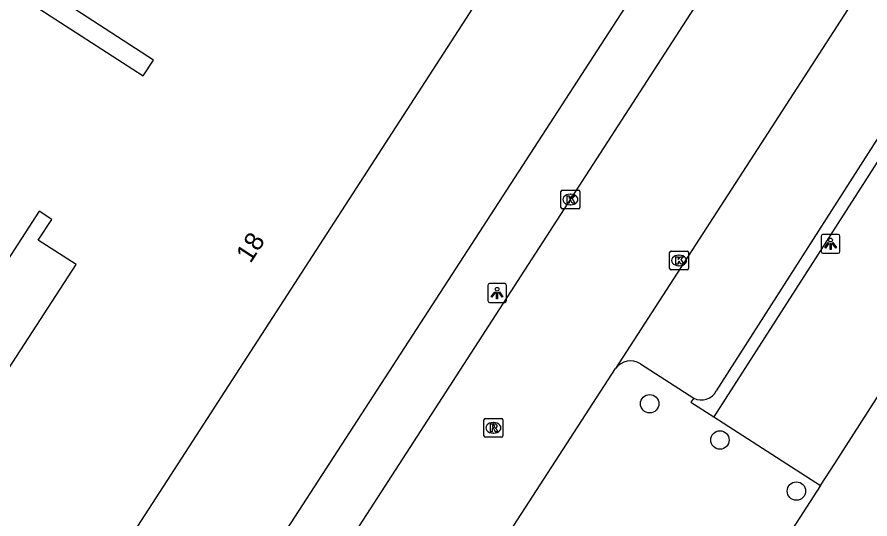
# Model space of a CAD drawing. Extents: x 161141 to 161601, y 381708 to 382245.
# Drawn here: x 161459.73 to 161504.99, y 382006.34 to 382032.97 of the extents above; entities that cross this region are included whole.
import ezdxf

# ---------------------------------------------------------------- set-up
doc = ezdxf.new("R2010")
doc.units = 0
for name, color, linetype in [('IMGEO_Boom', 7, 'Continuous'), ('IMGEO_Kolk', 7, 'Continuous'), ('IMGEO_Lichtpunt', 7, 'Continuous'), ('IMGEO_Pand', 7, 'Continuous'), ('IMGEO_Pand_nummerreeks', 7, 'Continuous'), ('IMGEO_Rijbaan_lokaal_open', 7, 'Continuous'), ('IMGEO_Rioolput', 7, 'Continuous'), ('IMGEO_Voetpad_open', 7, 'Continuous')]:
    doc.layers.add(name, color=color, linetype=linetype)

msp = doc.modelspace()

# ---------------------------------------------------------------- linework, layer by layer
at = {"layer": 'IMGEO_Boom'}
for centre in [(161493.303, 382012.455), (161497.03, 382010.529), (161501.091, 382007.818)]:
    msp.add_circle(centre, 0.489, dxfattribs=at)
at = {"layer": 'IMGEO_Kolk'}
for p, q in [((161488.595, 382022.863), (161488.595, 382023.715)), ((161488.67, 382023.789), (161489.522, 382023.789)), ((161489.083, 382023.569), (161489.108, 382023.569)), ((161489.596, 382023.715), (161489.596, 382022.863)), ((161489.106, 382023.009), (161489.081, 382023.009)), ((161489.522, 382022.789), (161488.67, 382022.789)), ((161494.363, 382019.63), (161494.363, 382020.482)), ((161494.438, 382020.556), (161495.29, 382020.556)), ((161494.851, 382020.336), (161494.876, 382020.336)), ((161495.364, 382020.482), (161495.364, 382019.63)), ((161494.874, 382019.776), (161494.849, 382019.776)), ((161495.29, 382019.556), (161494.438, 382019.556))]:
    msp.add_line(p, q, dxfattribs=at)
for points in [[(161488.595, 382022.863), (161488.595, 382023.715)], [(161488.67, 382023.789), (161489.522, 382023.789)], [(161488.916, 382023.489), (161489.039, 382023.489), (161489.039, 382023.338), (161489.169, 382023.489), (161489.333, 382023.489), (161489.187, 382023.338), (161489.34, 382023.089), (161489.188, 382023.089), (161489.103, 382023.253), (161489.039, 382023.186), (161489.039, 382023.089), (161488.916, 382023.089), (161488.916, 382023.489)], [(161489.596, 382023.715), (161489.596, 382022.863)], [(161489.522, 382022.789), (161488.67, 382022.789)], [(161494.363, 382019.63), (161494.363, 382020.482)], [(161494.438, 382020.556), (161495.29, 382020.556)], [(161494.684, 382020.256), (161494.807, 382020.256), (161494.807, 382020.105), (161494.937, 382020.256), (161495.101, 382020.256), (161494.955, 382020.105), (161495.108, 382019.856), (161494.956, 382019.856), (161494.871, 382020.02), (161494.807, 382019.953), (161494.807, 382019.856), (161494.684, 382019.856), (161494.684, 382020.256)], [(161495.364, 382020.482), (161495.364, 382019.63)], [(161495.29, 382019.556), (161494.438, 382019.556)]]:
    msp.add_lwpolyline(points, dxfattribs=at)
for centre, start, end in [((161488.672, 382023.713), 91.552, 178.448), ((161488.672, 382023.713), 91.552, 178.448), ((161489.52, 382023.713), 1.552, 88.448), ((161489.52, 382023.713), 1.552, 88.448), ((161488.672, 382022.865), 181.552, 268.448), ((161488.672, 382022.865), 181.552, 268.448), ((161489.52, 382022.865), 271.552, 358.448), ((161489.52, 382022.865), 271.552, 358.448), ((161494.44, 382020.48), 91.552, 178.448), ((161494.44, 382020.48), 91.552, 178.448), ((161495.288, 382020.48), 1.552, 88.448), ((161495.288, 382020.48), 1.552, 88.448), ((161494.44, 382019.632), 181.552, 268.448), ((161494.44, 382019.632), 181.552, 268.448), ((161495.288, 382019.632), 271.552, 358.448), ((161495.288, 382019.632), 271.552, 358.448)]:
    msp.add_arc(centre, 0.0765, start, end, dxfattribs=at)
for centre, major_axis, ratio, start_param, end_param in [((161489.082, 382023.289), (-0.387, 0.002), 0.722429, 4.712389, 7.853982), ((161489.107, 382023.289), (-0.39, 0.002), 0.717154, 1.570796, 4.712389), ((161494.85, 382020.056), (-0.387, 0.002), 0.722429, 4.712389, 7.853982), ((161494.875, 382020.056), (-0.39, 0.002), 0.717154, 1.570796, 4.712389)]:
    msp.add_ellipse(centre, major_axis=major_axis, ratio=ratio, start_param=start_param, end_param=end_param, dxfattribs=at)
at = {"layer": 'IMGEO_Lichtpunt'}
for p, q in [((161502.405, 382021.341), (161502.405, 382020.534)), ((161502.405, 382021.341), (161502.405, 382020.534)), ((161503.307, 382021.436), (161502.499, 382021.436)), ((161503.307, 382021.436), (161502.499, 382021.436)), ((161503.401, 382020.534), (161503.401, 382021.341)), ((161503.401, 382020.534), (161503.401, 382021.341)), ((161502.499, 382020.44), (161503.307, 382020.44)), ((161502.499, 382020.44), (161503.307, 382020.44)), ((161484.707, 382018.731), (161484.707, 382017.924)), ((161484.707, 382018.731), (161484.707, 382017.924)), ((161485.609, 382018.826), (161484.801, 382018.826)), ((161485.609, 382018.826), (161484.801, 382018.826)), ((161485.703, 382017.924), (161485.703, 382018.731)), ((161485.703, 382017.924), (161485.703, 382018.731)), ((161484.801, 382017.83), (161485.609, 382017.83)), ((161484.801, 382017.83), (161485.609, 382017.83))]:
    msp.add_line(p, q, dxfattribs=at)
for points in [[(161502.779, 382021.005), (161502.818, 382020.977), (161502.63, 382020.715), (161502.592, 382020.742), (161502.779, 382021.005)], [(161502.881, 382020.957), (161502.928, 382020.957), (161502.928, 382020.635), (161502.881, 382020.635), (161502.881, 382020.957)], [(161502.991, 382020.977), (161503.029, 382021.004), (161503.216, 382020.742), (161503.177, 382020.714), (161502.991, 382020.977)], [(161485.081, 382018.395), (161485.12, 382018.367), (161484.932, 382018.105), (161484.894, 382018.132), (161485.081, 382018.395)], [(161485.183, 382018.347), (161485.23, 382018.347), (161485.23, 382018.025), (161485.183, 382018.025), (161485.183, 382018.347)], [(161485.293, 382018.367), (161485.331, 382018.394), (161485.518, 382018.132), (161485.479, 382018.104), (161485.293, 382018.367)]]:
    msp.add_lwpolyline(points, dxfattribs=at)
for centre in [(161502.904, 382021.139), (161485.206, 382018.529)]:
    msp.add_circle(centre, 0.0994, dxfattribs=at)
for centre, start, end in [((161502.499, 382021.341), 90, 180), ((161502.499, 382021.341), 90, 180), ((161503.307, 382021.341), 0, 90), ((161503.307, 382021.341), 0, 90), ((161502.499, 382020.534), 180, 270), ((161502.499, 382020.534), 180, 270), ((161503.307, 382020.534), 270, 0), ((161503.307, 382020.534), 270, 360), ((161484.801, 382018.731), 90, 180), ((161484.801, 382018.731), 90, 180), ((161485.609, 382018.731), 0, 90), ((161485.609, 382018.731), 0, 90), ((161484.801, 382017.924), 180, 270), ((161484.801, 382017.924), 180, 270), ((161485.609, 382017.924), 270, 0), ((161485.609, 382017.924), 270, 360)]:
    msp.add_arc(centre, 0.0946, start, end, dxfattribs=at)
at = {"layer": 'IMGEO_Pand'}
for points in [[(161465.14, 382043.824), (161467.861, 382048.029), (161476.169, 382042.655), (161476.375, 382042.973), (161486.031, 382036.726), (161463.237, 382001.496), (161453.51, 382007.789)], [(161455.991, 382036.598), (161466.421, 382029.851), (161466.963, 382030.689), (161462.496, 382033.579), (161463.339, 382034.883), (161460.531, 382036.7), (161465.14, 382043.824)], [(161459.285, 382014.308), (161462.86, 382019.835), (161460.857, 382021.131), (161461.57, 382022.233), (161460.898, 382022.668), (161459.22, 382020.074)]]:
    msp.add_lwpolyline(points, dxfattribs=at)
at = {"layer": 'IMGEO_Rijbaan_lokaal_open'}
for points in [[(161464.955, 381985.959), (161500.799, 382041.385)], [(161504.966, 382035.175), (161491.489, 382014.315)], [(161485.898, 382005.698), (161491.489, 382014.315)]]:
    msp.add_lwpolyline(points, dxfattribs=at)
at = {"layer": 'IMGEO_Rioolput'}
for p, q in [((161484.583, 382011.677), (161485.435, 382011.677)), ((161484.508, 382010.751), (161484.508, 382011.603)), ((161484.996, 382011.457), (161485.021, 382011.457)), ((161485.509, 382011.603), (161485.509, 382010.751)), ((161485.019, 382010.897), (161484.994, 382010.897)), ((161485.435, 382010.677), (161484.583, 382010.677))]:
    msp.add_line(p, q, dxfattribs=at)
for points in [[(161484.583, 382011.677), (161485.435, 382011.677)], [(161484.508, 382010.751), (161484.508, 382011.603)], [(161485.097, 382011.375), (161484.845, 382011.377), (161484.845, 382010.977)], [(161485.023, 382011.296), (161484.969, 382011.296), (161484.969, 382011.215)], [(161484.969, 382011.215), (161485.021, 382011.215)], [(161485.509, 382011.603), (161485.509, 382010.751)], [(161484.845, 382010.977), (161484.969, 382010.977), (161484.969, 382011.139), (161484.98, 382011.139)], [(161485.027, 382011.11), (161485.098, 382010.977), (161485.238, 382010.977), (161485.173, 382011.103)], [(161485.435, 382010.677), (161484.583, 382010.677)]]:
    msp.add_lwpolyline(points, dxfattribs=at)
for centre, radius, start, end in [((161484.585, 382011.601), 0.0765, 91.552, 178.448), ((161484.585, 382011.601), 0.0765, 91.552, 178.448), ((161485.433, 382011.601), 0.0765, 1.552, 88.448), ((161485.433, 382011.601), 0.0765, 1.552, 88.448), ((161485.005, 382011.404), 0.19, 274.7715, 282.9687), ((161485.029, 382011.2), 0.0964, 77.0061, 93.1865), ((161485.043, 382011.257), 0.0378, 276.6634, 79.6772), ((161485.096, 382011.265), 0.109, 350.3612, 89.416), ((161485.094, 382011.265), 0.112, 277.5842, 350.9817), ((161484.585, 382010.753), 0.0765, 181.552, 268.448), ((161484.585, 382010.753), 0.0765, 181.552, 268.448), ((161484.979, 382011.086), 0.0533, 26.0293, 88.6989), ((161485.078, 382011.05), 0.108, 29.5134, 73.7905), ((161485.433, 382010.753), 0.0765, 271.552, 358.448), ((161485.433, 382010.753), 0.0765, 271.552, 358.448)]:
    msp.add_arc(centre, radius, start, end, dxfattribs=at)
for centre, major_axis, ratio, start_param, end_param in [((161484.995, 382011.177), (-0.387, 0.002), 0.722429, 4.712389, 7.853982), ((161485.02, 382011.177), (-0.39, 0.002), 0.717154, 1.570796, 4.712389)]:
    msp.add_ellipse(centre, major_axis=major_axis, ratio=ratio, start_param=start_param, end_param=end_param, dxfattribs=at)
at = {"layer": 'IMGEO_Voetpad_open'}
for points in [[(161462.38, 381987.777), (161470.3, 382000), (161498.24, 382043.117)], [(161508.122, 382030.748), (161508.66, 382030.403), (161496.714, 382011.755)], [(161496.841, 382013.134), (161508.122, 382030.748)], [(161502.377, 382008.114), (161503.136, 382009.288), (161516.685, 382030.422)], [(161492.819, 382014.575), (161495.645, 382012.744)], [(161495.645, 382012.744), (161495.494, 382012.545), (161496.714, 382011.755)], [(161496.714, 382011.755), (161502.377, 382008.114)], [(161502.377, 382008.114), (161496.146, 381998.479)]]:
    msp.add_lwpolyline(points, dxfattribs=at)
for centre, radius, start, end in [((161492.296, 382013.717), 1.005, 58.664, 143.4584), ((161496.039, 382013.564), 0.91, 244.3382, 331.7827)]:
    msp.add_arc(centre, radius, start, end, dxfattribs=at)

# ---------------------------------------------------------------- texts
at = {"layer": 'IMGEO_Pand_nummerreeks'}
msp.add_text('18', height=1, rotation=57.0952, dxfattribs=at).set_placement((161472.12, 382019.865))

doc.saveas('drawing.dxf')
